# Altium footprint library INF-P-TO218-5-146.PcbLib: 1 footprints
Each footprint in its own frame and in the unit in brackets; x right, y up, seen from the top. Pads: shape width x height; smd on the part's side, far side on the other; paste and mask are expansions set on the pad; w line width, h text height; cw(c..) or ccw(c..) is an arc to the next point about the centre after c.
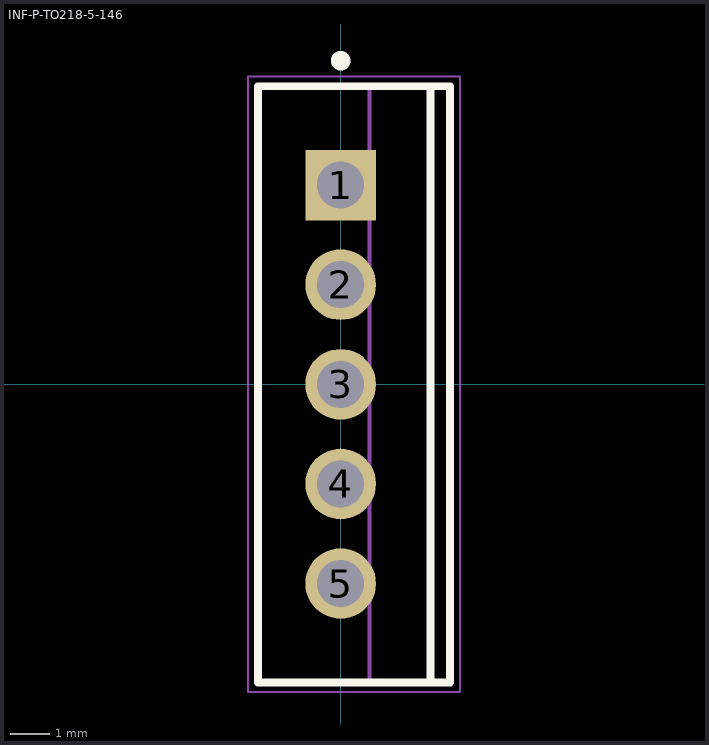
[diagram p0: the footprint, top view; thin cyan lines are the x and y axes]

## INF-P-TO218-5-146 [mm] "FM, 5-Leads, Body 15x12.5mm, Pitch 2.54mm"
height 22.2
pads (5):
  rect 1.8x1.8 hole 1.2: 1(0,5.08)
  round 1.8 hole 1.2: 2(0,2.54) 3(0,0) 4(0,-2.54) 5(0,-5.08)
Top Overlay:
  circle w0.25: c0,8.25 r0.125
  lines w0.2: 2.29,-7.6 2.29,7.6 ; -2.11,-7.6 -2.11,7.6 2.79,7.6 2.79,-7.6 -2.11,-7.6
Mechanical 13:
  lines w0.1: 0.74,-7.6 0.74,7.6 ; -2.11,-7.6 2.79,-7.6 2.79,7.6 -2.11,7.6 -2.11,-7.6
Mechanical 15:
  lines w0.05: -2.36,-7.85 3.04,-7.85 3.04,7.85 -2.36,7.85 -2.36,-7.85
  lines w0.1: -0.5,0 0.5,0 ; 0,-0.5 0,0.5
3D body: height 22.2, standoff 20.25, extent 0.74,-7.5 2.79,7.5
3D body: height 18.6, standoff 18.2, extent 0.74,-7.5 2.79,-2.05
3D body: height 18.6, standoff 18.2, extent 0.74,2.05 2.79,7.5
3D body: height 18.2, standoff 17.8, extent 0.74,-7.5 2.79,-2.05
3D body: height 18.2, standoff 17.8, extent 0.74,2.05 2.79,7.5
3D body: height 18.99, standoff 18.6, extent 0.74,-7.5 2.79,-2.011
3D body: height 18.99, standoff 18.6, extent 0.74,2.011 2.79,7.5
3D body: height 17.81, standoff 17.42, extent 0.74,-7.5 2.79,-2.011
3D body: height 17.81, standoff 17.42, extent 0.74,2.011 2.79,7.5
3D body: height 19.34, standoff 18.98, extent 0.74,-7.5 2.79,-1.894
3D body: height 19.34, standoff 18.98, extent 0.74,1.894 2.79,7.5
3D body: height 17.42, standoff 17.06, extent 0.74,-7.5 2.79,-1.894
3D body: height 17.42, standoff 17.06, extent 0.74,1.894 2.79,7.5
3D body: height 19.65, standoff 19.34, extent 0.74,-7.5 2.79,-1.705
3D body: height 19.65, standoff 19.34, extent 0.74,1.705 2.79,7.5
3D body: height 17.07, standoff 16.75, extent 0.74,-7.5 2.79,-1.705
3D body: height 17.07, standoff 16.75, extent 0.74,1.705 2.79,7.5
3D body: height 19.91, standoff 19.65, extent 0.74,-7.5 2.79,-1.45
3D body: height 19.91, standoff 19.65, extent 0.74,1.45 2.79,7.5
3D body: height 16.76, standoff 16.5, extent 0.74,-7.5 2.79,-1.45
3D body: height 16.76, standoff 16.5, extent 0.74,1.45 2.79,7.5
3D body: height 20.1, standoff 19.9, extent 0.74,-7.5 2.79,-1.139
3D body: height 20.1, standoff 19.9, extent 0.74,1.139 2.79,7.5
3D body: height 16.5, standoff 16.31, extent 0.74,-7.5 2.79,-1.139
3D body: height 16.5, standoff 16.31, extent 0.74,1.139 2.79,7.5
3D body: height 20.22, standoff 20.09, extent 0.74,-7.5 2.79,-0.785
3D body: height 20.22, standoff 20.09, extent 0.74,0.785 2.79,7.5
3D body: height 16.31, standoff 16.19, extent 0.74,-7.5 2.79,-0.785
3D body: height 16.31, standoff 16.19, extent 0.74,0.785 2.79,7.5
3D body: height 20.25, standoff 20.21, extent 0.74,-7.5 2.79,-0.4
3D body: height 20.25, standoff 20.21, extent 0.74,0.4 2.79,7.5
3D body: height 16.19, standoff 16.15, extent 0.74,-7.5 2.79,-0.4
3D body: height 16.19, standoff 16.15, extent 0.74,0.4 2.79,7.5
3D body: height 16.15, standoff 14.4, extent 0.74,-7.5 2.79,7.5
3D body: height 14.4, standoff 1.7, extent -2.11,-7.6 2.79,7.6
3D body: height 0, standoff -1.6, extent -0.29,-5.63 0.29,-4.53
3D body: height 1.7, standoff 0, extent -0.29,-5.73 0.29,-4.43
3D body: height 0, standoff -1.6, extent -0.29,-3.09 0.29,-1.99
3D body: height 1.7, standoff 0, extent -0.29,-3.19 0.29,-1.89
3D body: height 0, standoff -1.6, extent -0.29,-0.55 0.29,0.55
3D body: height 1.7, standoff 0, extent -0.29,-0.65 0.29,0.65
3D body: height 0, standoff -1.6, extent -0.29,1.99 0.29,3.09
3D body: height 1.7, standoff 0, extent -0.29,1.89 0.29,3.19
3D body: height 0, standoff -1.6, extent -0.29,4.53 0.29,5.63
3D body: height 1.7, standoff 0, extent -0.29,4.43 0.29,5.73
